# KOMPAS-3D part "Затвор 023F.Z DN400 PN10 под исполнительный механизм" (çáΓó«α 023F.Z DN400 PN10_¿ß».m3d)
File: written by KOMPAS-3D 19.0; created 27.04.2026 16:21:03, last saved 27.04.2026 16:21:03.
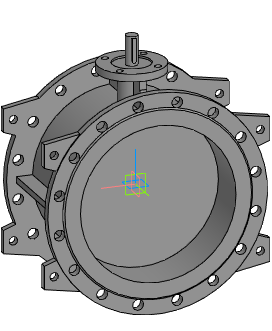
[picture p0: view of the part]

Document properties: Автор: Евгений; Полное имя файла: Z:\3.Личные\kachalov\3d для проектировщиков\1.7 Тип 023F.Z Затвор дисковый поворотный фланцевый с двумя эксцентриками\Затвор 023F.Z DN200-DN1600_исп\_stp_Затвор 023F.Z DN200-DN1600_исп\Затвор 023F.Z DN400 PN10_исп.m3d

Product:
- Part/product: Затвор 023F.Z DN400 PN10 под исполнительный механизм

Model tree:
1. Операция без истории:1  (labels: Затвор 023F.Z DN400 PN10 под исполнительный механизм)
